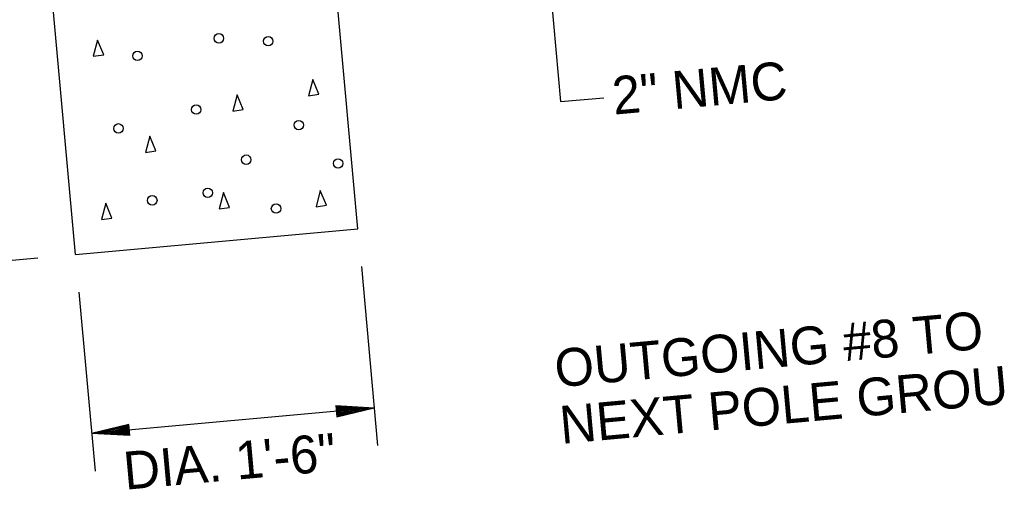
# Model space of a CAD drawing. Extents: x 1277218 to 1279252, y 196860 to 197529.
# Drawn here: x 1278336.3 to 1278454.9, y 197214.8 to 197271.8 of the extents above; entities that cross this region are included whole.
import ezdxf

# ---------------------------------------------------------------- set-up
doc = ezdxf.new("R2010")
doc.units = 0
doc.layers.add('R_Point Sym', color=7, linetype='Continuous')

msp = doc.modelspace()

# ---------------------------------------------------------------- linework, layer by layer
at = {"layer": 'R_Point Sym'}
for p, q in [((1278377.31, 197246.38), (1278371.1, 197314.95)), ((1278343.03, 197243.27), (1278336.82, 197311.84)), ((1278400.34, 197278.98), (1278401.9, 197261.8)), ((1278401.9, 197261.8), (1278407.17, 197262.28)), ((1278343.03, 197243.27), (1278377.31, 197246.38)), ((1278299.89, 197239.36), (1278338.46, 197242.86)), ((1278377.73, 197241.81), (1278379.7, 197220.09)), ((1278343.44, 197238.7), (1278345.41, 197216.99)), ((1278379.28, 197224.67), (1278345, 197221.56)), ((1278374.65, 197224.94), (1278379.28, 197224.67)), ((1278374.65, 197224.94), (1278374.77, 197223.57)), ((1278374.66, 197224.82), (1278378.52, 197224.6)), ((1278374.67, 197224.71), (1278377.73, 197224.52)), ((1278374.77, 197223.57), (1278379.28, 197224.67)), ((1278374.68, 197224.59), (1278376.97, 197224.46)), ((1278374.69, 197224.47), (1278376.2, 197224.39)), ((1278374.7, 197224.36), (1278375.43, 197224.32)), ((1278374.72, 197224.14), (1278375.43, 197224.32)), ((1278374.73, 197224.03), (1278376.2, 197224.39)), ((1278374.74, 197223.91), (1278376.97, 197224.46)), ((1278374.75, 197223.8), (1278377.73, 197224.52)), ((1278374.76, 197223.68), (1278378.52, 197224.6)), ((1278349.51, 197222.66), (1278345, 197221.56)), ((1278349.52, 197222.54), (1278345.76, 197221.63)), ((1278349.53, 197222.43), (1278346.55, 197221.7)), ((1278349.54, 197222.31), (1278347.31, 197221.77)), ((1278349.63, 197221.29), (1278349.51, 197222.66)), ((1278349.63, 197221.29), (1278345, 197221.56)), ((1278349.62, 197221.4), (1278345.76, 197221.63)), ((1278349.61, 197221.52), (1278346.55, 197221.7)), ((1278349.6, 197221.63), (1278347.31, 197221.77)), ((1278349.55, 197222.2), (1278348.08, 197221.84)), ((1278349.59, 197221.75), (1278348.08, 197221.84)), ((1278349.56, 197222.08), (1278348.85, 197221.91)), ((1278349.58, 197221.87), (1278348.85, 197221.91))]:
    msp.add_line(p, q, dxfattribs=at)
for points in [[(1278345.72, 197269.26), (1278345.2, 197267.3), (1278346.46, 197267.46), (1278345.72, 197269.26)], [(1278371.83, 197264.48), (1278371.31, 197262.52), (1278372.56, 197262.69), (1278371.83, 197264.48)], [(1278362.66, 197262.62), (1278362.14, 197260.66), (1278363.39, 197260.83), (1278362.66, 197262.62)], [(1278352.07, 197257.61), (1278351.55, 197255.65), (1278352.81, 197255.82), (1278352.07, 197257.61)], [(1278361.01, 197250.77), (1278360.49, 197248.81), (1278361.74, 197248.97), (1278361.01, 197250.77)], [(1278372.75, 197251.02), (1278372.24, 197249.06), (1278373.49, 197249.23), (1278372.75, 197251.02)], [(1278346.71, 197249.47), (1278346.19, 197247.51), (1278347.44, 197247.68), (1278346.71, 197249.47)]]:
    msp.add_lwpolyline(points, dxfattribs=at)
for centre in [(1278360.44, 197269.48), (1278366.43, 197269.13), (1278350.56, 197267.35), (1278357.69, 197260.84), (1278348.25, 197258.56), (1278370.14, 197258.95), (1278363.76, 197254.76), (1278374.91, 197254.3), (1278359.09, 197250.75), (1278352.36, 197249.83), (1278367.38, 197248.83)]:
    msp.add_circle(centre, 0.574, dxfattribs=at)

# ---------------------------------------------------------------- texts
for s, height, p in [('2" NMC', 4.59, (1278408.39, 197260.22)), ('OUTGOING #8 TO', 4.5899, (1278401.4, 197227.14)), ('NEXT POLE GROUND', 4.5899, (1278402.02, 197220.28)), ('DIA. 1\'-6"', 4.59, (1278349.08, 197214.72))]:
    msp.add_text(s, height=height, rotation=5.1779, dxfattribs=at).set_placement(p)

doc.saveas('drawing.dxf')
